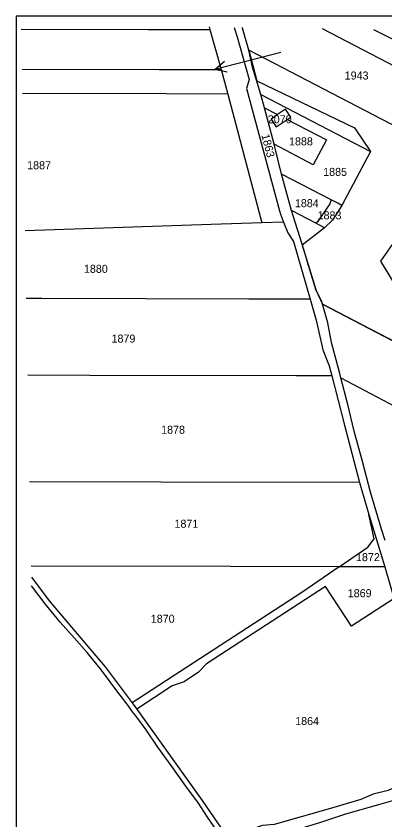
# Model space of a CAD drawing. Extents: x -584305 to -582773, y -1166873 to -1164718.
# Drawn here: x -584305 to -583983, y -1165476 to -1164773 of the extents above; entities that cross this region are included whole.
import ezdxf

# ---------------------------------------------------------------- set-up
doc = ezdxf.new("R2010")
doc.units = 0
for name, color, linetype in [('_Rám HC11-R', 7, 'Continuous'), ('_ZOV', 7, 'Continuous'), ('Hranice parcel', 7, 'Continuous'), ('Parcelní čísla', 7, 'Continuous')]:
    doc.layers.add(name, color=color, linetype=linetype)

msp = doc.modelspace()

# ---------------------------------------------------------------- linework, layer by layer
at = {"layer": '_Rám HC11-R'}
msp.add_lwpolyline([(-582820.03, -1166873.12), (-582820.03, -1164773.12), (-584305.03, -1164773.12), (-584305.03, -1166873.12), (-582820.03, -1166873.12)], dxfattribs=at)
msp.add_lwpolyline([(-583928.98, -1165081.35), (-583986.49, -1164987.28), (-583967.99, -1164961.13), (-583954.85, -1164923.82), (-583942.36, -1164931.66), (-583924.13, -1164896.6), (-583941.58, -1164886.27), (-584101.83, -1164802.98), (-584094.81, -1164829.69), (-584009.27, -1164870.93), (-583995.35, -1164891.63), (-584020.43, -1164938.66), (-584028.48, -1164951.62), (-584035.7, -1164958.26), (-584055.06, -1164973.28), (-584042.99, -1165013.09), (-584037.3, -1165024.95)], close=True, dxfattribs=at)
at = {"layer": '_ZOV'}
msp.add_line((-584073.78, -1164805.07), (-584131.38, -1164819.91), dxfattribs=at)
msp.add_lwpolyline([(-584120.54, -1164822.24), (-584131.38, -1164819.91), (-584123.02, -1164812.64)], dxfattribs=at)
at = {"layer": 'Hranice parcel'}
for p, q in [((-584136.29, -1164782.6), (-584135.64, -1164784.94)), ((-584135.64, -1164784.94), (-584126.01, -1164819.84)), ((-583956.67, -1164826.46), (-584037.5, -1164784.25)), ((-583947.23, -1164808.23), (-583992.46, -1164785)), ((-584126.01, -1164819.84), (-584120.06, -1164841.33)), ((-584120.06, -1164841.33), (-584090.48, -1164953.81)), ((-584088.14, -1164853.24), (-584091.16, -1164841.68)), ((-584079.67, -1164885.17), (-584088.14, -1164853.24)), ((-584088.14, -1164853.24), (-584076.59, -1164859.25)), ((-584073.2, -1164911.26), (-584079.67, -1164885.17)), ((-584064.56, -1164942.96), (-584073.2, -1164911.26)), ((-584029.68, -1164933.86), (-584073.2, -1164911.26)), ((-584043.31, -1164954.22), (-584064.56, -1164942.96)), ((-584071.34, -1164953.16), (-584090.48, -1164953.81)), ((-583928.98, -1165081.35), (-584037.3, -1165024.95)), ((-584004.96, -1165180.89), (-583996.84, -1165208.83)), ((-583996.84, -1165208.83), (-583983.04, -1165254.67)), ((-583983.04, -1165254.67), (-584022.77, -1165254.58)), ((-584203.2, -1165381.2), (-584207.26, -1165375.81)), ((-584203.74, -1165373.5), (-584199.68, -1165378.89))]:
    msp.add_line(p, q, dxfattribs=at)
for points in [[(-584300.45, -1164784.58), (-584189.89, -1164784.82), (-584135.64, -1164784.94)], [(-584114.4, -1164782.96), (-584112.02, -1164791.38), (-584101.48, -1164828.6), (-584103.83, -1164836.55), (-584088.97, -1164891.37), (-584074.9, -1164943.28), (-584074.11, -1164946.18), (-584071.34, -1164953.16)], [(-584101.83, -1164802.98), (-584107.21, -1164783.62), (-584107.33, -1164783.08)], [(-584091.16, -1164841.68), (-584098.46, -1164817.69), (-584101.83, -1164802.98)], [(-583924.13, -1164896.6), (-583941.58, -1164886.27), (-584101.83, -1164802.98)], [(-584299.81, -1164819.45), (-584180.12, -1164819.72), (-584126.01, -1164819.84)], [(-584120.06, -1164841.33), (-584173.88, -1164841.17), (-584299.42, -1164840.8)], [(-584091.16, -1164841.68), (-583995.35, -1164891.63), (-584020.43, -1164938.66)], [(-584068.32, -1164863.56), (-584065.1, -1164861.38), (-584069.75, -1164854.62), (-584076.59, -1164859.25)], [(-584076.59, -1164859.25), (-584082.28, -1164863.1), (-584077.69, -1164869.91), (-584068.32, -1164863.56)], [(-584068.32, -1164863.56), (-584033.99, -1164881.43), (-584045.57, -1164903.16), (-584079.67, -1164885.17)], [(-584029.68, -1164933.86), (-584030.98, -1164937.12), (-584041.73, -1164953.04), (-584043.31, -1164954.22)], [(-584020.43, -1164938.66), (-584023.92, -1164936.53), (-584029.68, -1164933.86)], [(-584037.3, -1165024.95), (-584038.16, -1165021.95), (-584042.99, -1165013.09), (-584050.52, -1164988.21), (-584053.61, -1164977.12), (-584064.56, -1164942.96)], [(-584020.43, -1164938.66), (-584028.48, -1164951.62), (-584035.7, -1164958.26), (-584043.31, -1164954.22)], [(-584090.48, -1164953.81), (-584134.71, -1164955.31), (-584297.22, -1164960.82)], [(-584071.34, -1164953.16), (-584067.63, -1164962.48), (-584062.83, -1164970.07), (-584048.18, -1165020.65)], [(-584048.18, -1165020.65), (-584070.46, -1165020.6), (-584101.61, -1165020.53), (-584282.43, -1165020.13), (-584296.13, -1165020.1)], [(-584048.18, -1165020.65), (-584042.91, -1165038.81), (-584037.18, -1165064.8), (-584031.46, -1165078.76), (-584029.16, -1165087.65)], [(-584021.34, -1165089.39), (-584022.33, -1165085.67), (-584029.5, -1165058.59), (-584032.63, -1165041.29), (-584037.3, -1165024.95)], [(-584029.16, -1165087.65), (-584060.23, -1165087.58), (-584240.73, -1165087.18), (-584294.91, -1165087.06)], [(-584029.16, -1165087.65), (-584018.01, -1165130.6), (-584004.96, -1165180.89)], [(-583982.63, -1165231.56), (-583985.75, -1165221.62), (-583995.35, -1165189.21), (-584002.45, -1165162.55), (-584009.56, -1165135.88), (-584015.15, -1165112.74), (-584021.34, -1165089.39)], [(-584021.34, -1165089.39), (-583953, -1165125.34), (-583904.11, -1165151.07)], [(-584004.96, -1165180.89), (-584178.59, -1165180.51), (-584293.2, -1165180.26)], [(-584022.77, -1165254.58), (-583997.85, -1165237.48), (-583992.24, -1165229.99), (-583996.84, -1165208.83)], [(-584022.77, -1165254.58), (-584117.85, -1165254.37), (-584291.84, -1165253.99)], [(-584022.77, -1165254.58), (-584055.51, -1165277.05), (-584203.74, -1165373.5)], [(-583983.04, -1165254.67), (-583977.35, -1165273.76), (-583974.84, -1165282.18)], [(-584291.66, -1165263.71), (-584276.18, -1165284.38), (-584227.24, -1165341.86), (-584203.74, -1165373.5)], [(-584207.26, -1165375.81), (-584216.08, -1165364.12), (-584230.46, -1165344.81), (-584242.87, -1165329.46), (-584254.33, -1165316.55), (-584266.48, -1165302.89), (-584279.48, -1165286.98), (-584291.53, -1165271.1)], [(-583974.84, -1165282.18), (-584012.07, -1165306.46), (-584034.84, -1165271.61), (-584138.63, -1165339.21), (-584145.7, -1165346.69), (-584158.2, -1165355.08), (-584168.81, -1165358.7), (-584199.68, -1165378.89)], [(-583974.84, -1165282.18), (-583954.94, -1165348.93), (-583952.24, -1165368.22), (-583945.43, -1165383.61), (-583944.47, -1165391.31), (-583943.78, -1165404.8), (-583949.92, -1165432.02), (-583955.76, -1165438.7), (-583979.99, -1165450.08), (-583993.12, -1165453.3), (-584003.91, -1165458.08), (-584032.27, -1165466.39), (-584079.46, -1165479.88), (-584089.8, -1165480.66), (-584109.32, -1165487.31), (-584114.38, -1165490.11)], [(-584199.68, -1165378.89), (-584142.41, -1165458.77), (-584122.2, -1165488.62), (-584114.38, -1165490.11)], [(-584127.54, -1165493.29), (-584126.7, -1165489.49), (-584137.68, -1165473.5), (-584145.63, -1165461.29), (-584156.82, -1165446.27), (-584169.56, -1165428.1), (-584181.07, -1165412.34), (-584191.49, -1165397.12), (-584200.37, -1165384.95), (-584203.2, -1165381.2)], [(-583953.93, -1165452.64), (-583988.32, -1165462.57), (-584017.19, -1165470.76), (-584039.23, -1165478.13), (-584060.02, -1165484.43), (-584082.01, -1165490.99), (-584105.29, -1165498.3), (-584107.56, -1165499.38), (-584111.74, -1165503.97), (-584113.23, -1165508.57)]]:
    msp.add_lwpolyline(points, dxfattribs=at)

# ---------------------------------------------------------------- texts
at = {"layer": 'Parcelní čísla'}
for s, p in [('1943', (-584017.98, -1164828.56)), ('2070', (-584085.15, -1164866.83)), ('1888', (-584066.61, -1164886.15)), ('1887', (-584295.36, -1164907.03)), ('1885', (-584036.77, -1164912.81)), ('1884', (-584061.48, -1164940.17)), ('1883', (-584041.63, -1164950.82)), ('1880', (-584245.76, -1164997.55)), ('1879', (-584221.65, -1165058.53)), ('1878', (-584178.31, -1165138.23)), ('1871', (-584166.65, -1165220.4)), ('1872', (-584008.09, -1165249.59)), ('1869', (-584015.3, -1165281.1)), ('1870', (-584187.36, -1165303.44)), ('1864', (-584061.22, -1165392.86))]:
    msp.add_text(s, height=7, dxfattribs=at).set_placement(p)
msp.add_text('1863', height=7, rotation=284, dxfattribs=at).set_placement((-584090.76, -1164877.13))

doc.saveas('drawing.dxf')
